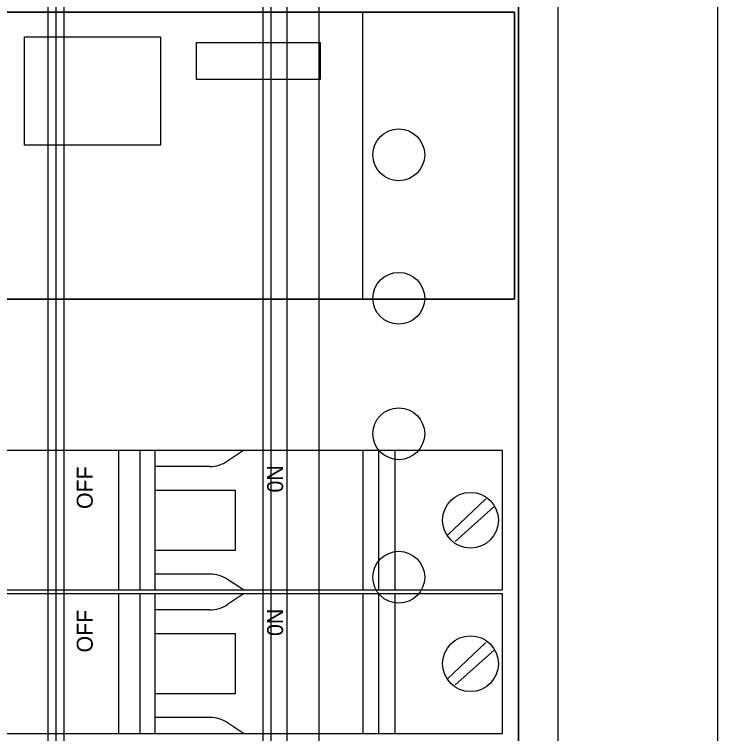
# Model space of a CAD drawing. Extents: x 0 to 4205, y 0 to 2970.
# Drawn here: x 1098.8 to 1187, y 1047.1 to 1137.3 of the extents above; entities that cross this region are included whole.
import ezdxf

# ---------------------------------------------------------------- set-up
doc = ezdxf.new("R2010")
doc.units = 0
doc.layers.add('02___PRT_ALL_AXES', color=7, linetype='Continuous')
doc.layers.add('Level 1', color=7, linetype='Continuous')

# ---------------------------------------------------------------- blocks, each defined once
blk = doc.blocks.new('NCX-2418-3U')
for p, q in [((15, 137.85), (15, -94.15)), ((-44, -99.15), (-44, 132.85)), ((-43, -99.15), (-43, 132.85)), ((-42, -99.15), (-42, 132.85)), ((-17, -99.15), (-17, 132.85)), ((-16, -99.15), (-16, 132.85)), ((-14, -91.15), (-14, 124.85)), ((-10, -91.15), (-10, 124.85))]:
    blk.add_line(p, q)
blk.add_lwpolyline([(15, -94.15), (15, 137.85), (10, 142.85), (-57.258, 142.85), (-57.258, 163.65)])
for centre in [(0, 53), (0, 18)]:
    blk.add_circle(centre, 3.25)
at = {"layer": '02___PRT_ALL_AXES'}
for centre in [(0, 35), (0, 0)]:
    blk.add_circle(centre, 3.25, dxfattribs=at)

msp = doc.modelspace()

# ---------------------------------------------------------------- linework, layer by layer
at = {"layer": 'Level 1'}
for p, q in [((1142.508, 1101.593), (1142.508, 1137.593)), ((1160.008, 1082.593), (1077.008, 1082.593)), ((1111.855, 1082.593), (1111.855, 1065.093)), ((1114.508, 1082.593), (1114.508, 1065.093)), ((1116.423, 1065.15), (1116.423, 1082.569)), ((1127.508, 1082.593), (1125.515, 1081.265)), ((1142.508, 1082.593), (1142.508, 1065.093)), ((1144.508, 1065.093), (1144.508, 1082.593)), ((1146.508, 1082.593), (1146.508, 1065.093)), ((1160.008, 1065.093), (1160.008, 1082.593)), ((1123.297, 1080.593), (1116.423, 1080.593)), ((1126.508, 1077.593), (1116.423, 1077.593)), ((1126.508, 1070.093), (1126.508, 1077.593)), ((1157.932, 1076.517), (1153.084, 1071.919)), ((1154.084, 1071.169), (1158.932, 1075.517)), ((1116.423, 1070.093), (1126.508, 1070.093)), ((1123.297, 1067.093), (1116.423, 1067.093)), ((1127.508, 1065.093), (1125.515, 1066.421)), ((1077.008, 1065.093), (1160.008, 1065.093)), ((1160.008, 1064.593), (1077.008, 1064.593)), ((1111.855, 1064.593), (1111.855, 1047.093)), ((1114.508, 1064.593), (1114.508, 1047.093)), ((1116.423, 1047.15), (1116.423, 1064.569)), ((1127.508, 1064.593), (1125.515, 1063.265)), ((1142.508, 1064.593), (1142.508, 1047.093)), ((1144.508, 1047.093), (1144.508, 1064.593)), ((1146.508, 1064.593), (1146.508, 1047.093)), ((1160.008, 1047.093), (1160.008, 1064.593)), ((1123.297, 1062.593), (1116.423, 1062.593)), ((1126.508, 1059.593), (1116.423, 1059.593)), ((1126.508, 1052.093), (1126.508, 1059.593)), ((1157.932, 1058.517), (1153.084, 1053.919)), ((1154.084, 1053.169), (1158.932, 1057.517)), ((1116.423, 1052.093), (1126.508, 1052.093)), ((1123.297, 1049.093), (1116.423, 1049.093)), ((1127.508, 1047.093), (1125.515, 1048.421)), ((1077.008, 1047.093), (1160.008, 1047.093))]:
    msp.add_line(p, q, dxfattribs=at)
msp.add_lwpolyline([(1089.987, 963.143), (1167.008, 963.143), (1167.008, 1213.143), (1089.749, 1213.143)], dxfattribs=at)
for points in [[(1187.008, 963.143), (1167.008, 963.143), (1167.008, 1213.143), (1187.008, 1213.143)], [(1161.508, 1101.593), (1161.508, 1137.593), (1075.508, 1137.593), (1075.508, 1101.593)], [(1075.508, 1101.593), (1075.508, 1137.593), (1161.508, 1137.593), (1161.508, 1101.593)], [(1100.054, 1120.915), (1100.054, 1134.499), (1117.102, 1134.499), (1117.102, 1120.915)], [(1121.632, 1129.137), (1121.632, 1133.784), (1137.13, 1133.784), (1137.13, 1129.137)], [(1160.008, 1065.093), (1160.008, 1082.593), (1077.008, 1082.593), (1077.008, 1065.093)], [(1160.008, 1065.093), (1160.008, 1082.593), (1077.008, 1082.593), (1077.008, 1065.093)], [(1160.008, 1047.093), (1160.008, 1064.593), (1077.008, 1064.593), (1077.008, 1047.093)], [(1160.008, 1047.093), (1160.008, 1064.593), (1077.008, 1064.593), (1077.008, 1047.093)]]:
    msp.add_lwpolyline(points, close=True, dxfattribs=at)
for centre in [(1156.008, 1073.843), (1156.008, 1055.843)]:
    msp.add_circle(centre, 3.5, dxfattribs=at)
for centre, start, end in [((1123.297, 1084.593), 270, 303.69007), ((1123.297, 1063.093), 56.30993, 90), ((1123.297, 1066.593), 270, 303.69007), ((1123.297, 1045.093), 56.30993, 90)]:
    msp.add_arc(centre, 4, start, end, dxfattribs=at)

# ---------------------------------------------------------------- block references
msp.add_blockref('NCX-2418-3U', (1147.008, 1066.693))

# ---------------------------------------------------------------- texts
for s, p in [('OFF', (1108.609, 1075.252)), ('0N', (1132.49, 1077.318)), ('OFF', (1108.609, 1057.252)), ('0N', (1132.49, 1059.318))]:
    msp.add_text(s, height=2, rotation=90, dxfattribs=at).set_placement(p)

doc.saveas('drawing.dxf')
